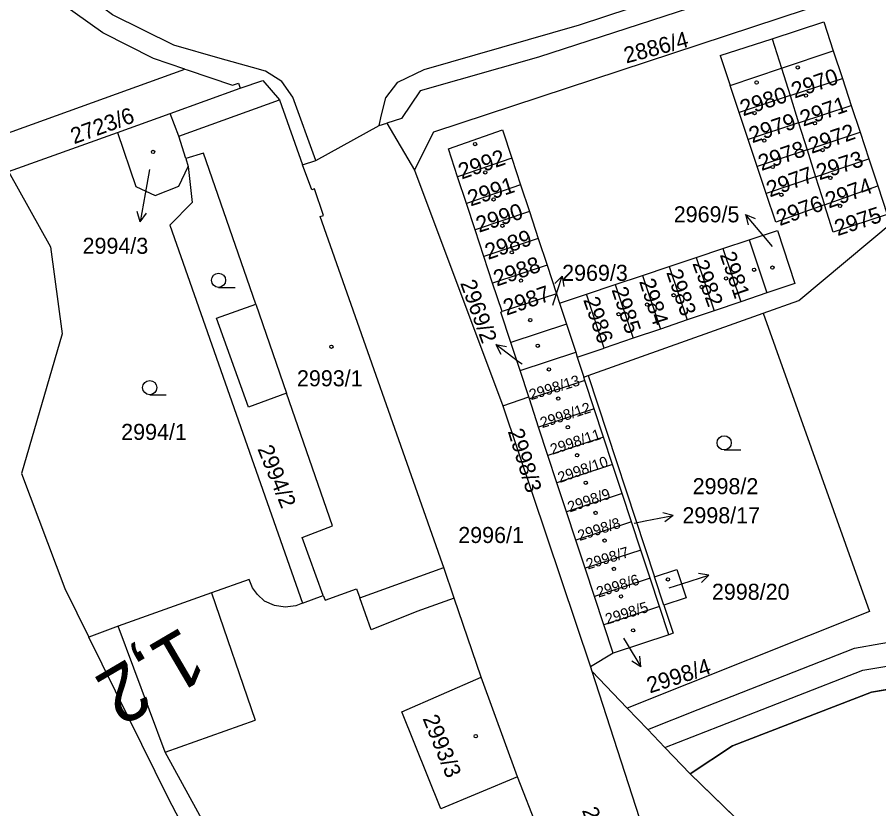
# Model space of a CAD drawing. Extents: x -738085 to -734306, y -1122197 to -1119753.
# Drawn here: x -735225.5 to -735134.3, y -1120249.4 to -1120165.6 of the extents above; entities that cross this region are included whole.
import ezdxf

# ---------------------------------------------------------------- set-up
doc = ezdxf.new("R2010")
doc.units = 0
for name, color, linetype in [('Hranice parcel', 7, 'Continuous'), ('Parcelní čísla', 7, 'Continuous'), ('Pop  PČ popisy', 7, 'Continuous'), ('SŽDC', 7, 'Continuous'), ('Vnitřní kresba', 7, 'Continuous'), ('Vrstva 53', 7, 'Continuous'), ('Vrstva 7', 7, 'Continuous'), ('Značky budov', 7, 'Continuous'), ('Značky kultur', 7, 'Continuous')]:
    doc.layers.add(name, color=color, linetype=linetype)

msp = doc.modelspace()

# ---------------------------------------------------------------- linework, layer by layer
at = {"layer": 'Hranice parcel'}
for p, q in [((-735144.59, -1120170.98), (-735143.67, -1120173.89)), ((-735143.67, -1120173.89), (-735138.14, -1120172.07)), ((-735138.14, -1120172.07), (-735137.2, -1120174.92)), ((-735209.31, -1120175.8), (-735201.89, -1120173.11)), ((-735143.67, -1120173.89), (-735149.07, -1120175.67)), ((-735143.67, -1120173.89), (-735142.77, -1120176.76)), ((-735148.12, -1120178.53), (-735149.07, -1120175.67)), ((-735142.77, -1120176.76), (-735137.2, -1120174.92)), ((-735137.2, -1120174.92), (-735136.26, -1120177.77)), ((-735214.89, -1120177.8), (-735209.31, -1120175.8)), ((-735193.9, -1120180.77), (-735187.2, -1120177.07)), ((-735187.2, -1120177.07), (-735186.39, -1120176.82)), ((-735186.39, -1120176.82), (-735183.44, -1120181.78)), ((-735142.77, -1120176.76), (-735148.12, -1120178.53)), ((-735142.77, -1120176.76), (-735141.86, -1120179.64)), ((-735226.43, -1120181.92), (-735214.89, -1120177.8)), ((-735141.86, -1120179.64), (-735136.26, -1120177.77)), ((-735136.26, -1120177.77), (-735135.33, -1120180.6)), ((-735147.16, -1120181.41), (-735148.12, -1120178.53)), ((-735141.86, -1120179.64), (-735147.16, -1120181.41)), ((-735141.86, -1120179.64), (-735140.97, -1120182.48)), ((-735207.67, -1120180.55), (-735207.41, -1120181.38)), ((-735195.32, -1120181.21), (-735193.9, -1120180.77)), ((-735173.15, -1120180.5), (-735178.88, -1120182.49)), ((-735173.15, -1120180.5), (-735172.22, -1120183.33)), ((-735140.97, -1120182.48), (-735135.33, -1120180.6)), ((-735135.33, -1120180.6), (-735134.39, -1120183.46)), ((-735183.44, -1120181.78), (-735174.09, -1120206.76)), ((-735146.22, -1120184.24), (-735147.16, -1120181.41)), ((-735177.95, -1120185.3), (-735178.88, -1120182.49)), ((-735140.97, -1120182.48), (-735146.22, -1120184.24)), ((-735140.97, -1120182.48), (-735140.03, -1120185.46)), ((-735172.22, -1120183.33), (-735177.95, -1120185.3)), ((-735172.22, -1120183.33), (-735171.28, -1120186.18)), ((-735140.03, -1120185.46), (-735134.39, -1120183.46)), ((-735177.03, -1120188.11), (-735177.95, -1120185.3)), ((-735171.28, -1120186.18), (-735177.03, -1120188.11)), ((-735171.28, -1120186.18), (-735170.35, -1120189.02)), ((-735176.1, -1120190.93), (-735177.03, -1120188.11)), ((-735170.35, -1120189.02), (-735176.1, -1120190.93)), ((-735170.35, -1120189.02), (-735169.41, -1120191.85)), ((-735150.78, -1120190.1), (-735148, -1120189.17)), ((-735148, -1120189.17), (-735146.13, -1120194.79)), ((-735153.61, -1120191.04), (-735150.78, -1120190.1)), ((-735150.78, -1120190.1), (-735148.9, -1120195.73)), ((-735175.17, -1120193.74), (-735176.1, -1120190.93)), ((-735156.46, -1120191.99), (-735153.61, -1120191.04)), ((-735153.61, -1120191.04), (-735151.72, -1120196.68)), ((-735169.41, -1120191.85), (-735175.17, -1120193.74)), ((-735169.41, -1120191.85), (-735168.41, -1120194.89)), ((-735159.3, -1120192.94), (-735156.46, -1120191.99)), ((-735156.46, -1120191.99), (-735154.56, -1120197.65)), ((-735162.18, -1120193.89), (-735159.3, -1120192.94)), ((-735159.3, -1120192.94), (-735157.41, -1120198.61)), ((-735174.17, -1120196.77), (-735175.17, -1120193.74)), ((-735162.18, -1120193.89), (-735160.29, -1120199.59)), ((-735146.13, -1120194.79), (-735148.9, -1120195.73)), ((-735168.41, -1120194.89), (-735174.17, -1120196.77)), ((-735148.9, -1120195.73), (-735151.72, -1120196.68)), ((-735165.05, -1120203.54), (-735146.53, -1120196.94)), ((-735151.72, -1120196.68), (-735154.56, -1120197.65)), ((-735167.36, -1120198.09), (-735173.26, -1120200.03)), ((-735167.36, -1120198.09), (-735166.37, -1120201.08)), ((-735154.56, -1120197.65), (-735157.41, -1120198.61)), ((-735157.41, -1120198.61), (-735160.29, -1120199.59)), ((-735172.27, -1120203.02), (-735173.26, -1120200.03)), ((-735172.27, -1120203.02), (-735166.37, -1120201.08)), ((-735171.35, -1120205.79), (-735172.27, -1120203.02)), ((-735165.52, -1120203.7), (-735165.05, -1120203.54)), ((-735165.39, -1120204.07), (-735165.52, -1120203.7)), ((-735165.05, -1120203.54), (-735158.02, -1120224.86)), ((-735165.39, -1120204.07), (-735171.28, -1120206.01)), ((-735164.41, -1120207.07), (-735165.39, -1120204.07)), ((-735174.09, -1120206.76), (-735171.35, -1120205.79)), ((-735171.28, -1120206.01), (-735171.35, -1120205.79)), ((-735170.3, -1120209), (-735171.28, -1120206.01)), ((-735174.09, -1120206.76), (-735164.81, -1120234.38)), ((-735164.41, -1120207.07), (-735170.3, -1120209)), ((-735163.42, -1120210.06), (-735164.41, -1120207.07)), ((-735169.31, -1120212), (-735170.3, -1120209)), ((-735163.42, -1120210.06), (-735169.31, -1120212)), ((-735162.47, -1120212.95), (-735163.42, -1120210.06)), ((-735168.36, -1120214.89), (-735169.31, -1120212)), ((-735162.47, -1120212.95), (-735168.36, -1120214.89)), ((-735161.46, -1120216.04), (-735162.47, -1120212.95)), ((-735167.34, -1120217.98), (-735168.36, -1120214.89)), ((-735161.46, -1120216.04), (-735167.34, -1120217.98)), ((-735160.47, -1120219.03), (-735161.46, -1120216.04)), ((-735166.36, -1120220.97), (-735167.34, -1120217.98)), ((-735160.47, -1120219.03), (-735166.36, -1120220.97)), ((-735159.48, -1120222.03), (-735160.47, -1120219.03)), ((-735165.37, -1120223.96), (-735166.36, -1120220.97)), ((-735159.48, -1120222.03), (-735165.37, -1120223.96)), ((-735158.49, -1120225.02), (-735159.48, -1120222.03)), ((-735164.38, -1120226.96), (-735165.37, -1120223.96)), ((-735157.04, -1120227.85), (-735158.02, -1120224.86)), ((-735158.49, -1120225.02), (-735164.38, -1120226.96)), ((-735157.51, -1120228.01), (-735158.49, -1120225.02)), ((-735195.3, -1120227.66), (-735196, -1120227.93)), ((-735163.4, -1120229.95), (-735164.38, -1120226.96)), ((-735157.51, -1120228.01), (-735163.4, -1120229.95)), ((-735156.53, -1120231), (-735157.51, -1120228.01)), ((-735214.81, -1120230.09), (-735217.93, -1120231.25)), ((-735162.42, -1120232.94), (-735163.4, -1120229.95)), ((-735156.53, -1120231), (-735162.42, -1120232.94)), ((-735162.42, -1120232.94), (-735164.81, -1120234.38)), ((-735164.81, -1120234.38), (-735164.65, -1120234.85)), ((-735160.91, -1120238.77), (-735164.65, -1120234.85)), ((-735164.65, -1120234.85), (-735158.13, -1120255.05)), ((-735184.78, -1120239.17), (-735176.37, -1120235.48)), ((-735172.55, -1120246.06), (-735176.37, -1120235.48)), ((-735158.75, -1120241.02), (-735160.91, -1120238.77)), ((-735156.93, -1120242.93), (-735158.75, -1120241.02)), ((-735154.27, -1120245.72), (-735156.93, -1120242.93)), ((-735168.74, -1120255.72), (-735172.55, -1120246.06))]:
    msp.add_line(p, q, dxfattribs=at)
for points in [[(-735187.2, -1120177.07), (-735186.92, -1120175.94), (-735186.47, -1120174.12), (-735185.21, -1120172.48), (-735182.42, -1120171.13), (-735165.98, -1120166.38), (-735013.95, -1120116.34), (-735003.48, -1120113.01), (-735000.64, -1120112.19), (-735000, -1120112.13), (-734996.62, -1120111.83), (-734988.63, -1120112.11), (-734951.68, -1120115.51), (-734795.1, -1120131), (-734756.12, -1120134.99), (-734754.2, -1120137.32), (-734753.31, -1120137.78), (-734734.93, -1120139.52), (-734728.17, -1120141.08), (-734724.68, -1120142.84), (-734723.73, -1120143.69)], [(-735193.9, -1120180.77), (-735196.33, -1120174.06), (-735197.48, -1120172.4), (-735199.22, -1120171.31), (-735200.58, -1120170.92), (-735204.03, -1120169.95), (-735208.93, -1120168.56), (-735215.43, -1120165.33), (-735220.17, -1120161.76), (-735223.18, -1120159.07), (-735230.74, -1120150.98), (-735240.02, -1120140.46), (-735244.13, -1120135.8)], [(-735207.77, -1120171.07), (-735211.09, -1120169.95), (-735216.45, -1120167.23), (-735220.95, -1120164.02), (-735226.04, -1120159.26), (-735234.12, -1120150.47), (-735242.12, -1120141.37), (-735242.83, -1120140.56)], [(-735087.85, -1120146.72), (-735088.13, -1120146.35), (-735133.32, -1120161.4), (-735138.8, -1120162.57), (-735140.07, -1120160.51), (-735141.06, -1120160.29), (-735170.32, -1120169.83), (-735182.85, -1120173.37), (-735184.82, -1120176.33), (-735186.39, -1120176.82)], [(-735183.44, -1120181.78), (-735181.38, -1120177.73), (-735088.44, -1120147.09)], [(-735144.59, -1120170.98), (-735139.1, -1120169.14), (-735138.14, -1120172.07)], [(-735228.19, -1120182.96), (-735229.89, -1120179.07), (-735207.77, -1120171.07)], [(-735207.77, -1120171.07), (-735207.53, -1120171.16), (-735202.7, -1120172.79), (-735202.09, -1120172.56), (-735201.89, -1120173.11)], [(-735149.07, -1120175.67), (-735150.03, -1120172.8), (-735144.59, -1120170.98)], [(-735201.89, -1120173.11), (-735199.52, -1120172.3), (-735197.74, -1120174.35), (-735195.32, -1120181.21)], [(-735207.67, -1120180.55), (-735208.4, -1120178.17), (-735209.31, -1120175.8)], [(-735178.88, -1120182.49), (-735179.86, -1120179.52), (-735174.14, -1120177.51), (-735173.15, -1120180.5)], [(-735214.89, -1120177.8), (-735212.94, -1120183.51), (-735210.89, -1120184.46), (-735208.41, -1120183.49), (-735207.41, -1120181.38)], [(-735195.3, -1120227.66), (-735193.1, -1120226.83), (-735195.34, -1120220.68), (-735192.12, -1120219.45), (-735196.99, -1120205.39), (-735201.03, -1120206.88), (-735204.4, -1120197.47), (-735200.25, -1120195.98), (-735205.79, -1120180), (-735207.67, -1120180.55)], [(-735226.43, -1120181.92), (-735221.97, -1120189.91), (-735220.76, -1120199.13), (-735225.06, -1120213.91), (-735220.47, -1120226.11), (-735217.93, -1120231.25)], [(-735207.41, -1120181.38), (-735206.99, -1120185.22), (-735209.34, -1120187.6), (-735195.3, -1120227.66)], [(-735176.37, -1120235.48), (-735179.23, -1120227.13), (-735180.34, -1120223.87), (-735180.47, -1120223.49), (-735193.42, -1120186.69), (-735193.07, -1120186.57), (-735194.04, -1120183.78), (-735194.33, -1120183.88), (-735195.32, -1120181.21)], [(-735134.39, -1120183.46), (-735133.4, -1120186.47), (-735139.12, -1120188.35), (-735140.03, -1120185.46)], [(-735140.03, -1120185.46), (-735145.2, -1120187.29), (-735146.22, -1120184.24)], [(-735146.53, -1120196.94), (-735142.76, -1120195.6), (-735130.27, -1120185.19)], [(-735148, -1120189.17), (-735145.02, -1120188.18), (-735143.17, -1120193.79), (-735146.13, -1120194.79)], [(-735160.29, -1120199.59), (-735163.37, -1120200.63), (-735165.23, -1120194.91), (-735162.18, -1120193.89)], [(-735168.41, -1120194.89), (-735168.09, -1120195.86), (-735167.36, -1120198.09)], [(-735173.26, -1120200.03), (-735174.3, -1120196.83), (-735174.17, -1120196.77)], [(-735146.53, -1120196.94), (-735135.27, -1120228.55), (-735160.91, -1120238.77)], [(-735166.37, -1120201.08), (-735166.21, -1120201.59), (-735165.52, -1120203.7)], [(-735156.93, -1120242.93), (-735151.15, -1120240.68), (-735135.96, -1120234.75), (-735114.78, -1120231.21), (-735102.36, -1120229.14), (-735095.09, -1120227.37), (-735088.56, -1120221.64)], [(-735158.02, -1120224.86), (-735155.65, -1120224.08), (-735154.66, -1120227.07), (-735157.04, -1120227.85)], [(-735154.27, -1120245.72), (-735149.78, -1120242.77), (-735135.06, -1120237.08), (-735101.77, -1120231.55), (-735094.5, -1120229.78), (-735087.7, -1120224.18)], [(-735200.96, -1120225.14), (-735204.93, -1120226.56), (-735214.81, -1120230.09)], [(-735196, -1120227.93), (-735197.14, -1120228.08), (-735198.28, -1120227.9), (-735199.31, -1120227.44), (-735200.08, -1120226.75), (-735200.6, -1120226.01), (-735200.96, -1120225.14)], [(-735157.04, -1120227.85), (-735156.06, -1120230.84), (-735156.53, -1120231)], [(-735158.75, -1120241.02), (-735153.4, -1120238.91), (-735136.86, -1120232.42), (-735134.06, -1120231.94), (-735115.58, -1120228.85)], [(-735197.46, -1120266.06), (-735209.83, -1120243.45), (-735214.81, -1120230.09)], [(-735190.45, -1120282.92), (-735199.82, -1120266.86), (-735209.49, -1120248.33), (-735217.93, -1120231.25)], [(-735172.55, -1120246.06), (-735180.64, -1120249.42), (-735184.78, -1120239.17)], [(-735126.91, -1120271.38), (-735136.63, -1120262.8), (-735138.78, -1120260.72), (-735140.3, -1120259.25), (-735154.27, -1120245.72)]]:
    msp.add_lwpolyline(points, dxfattribs=at)
at = {"layer": 'Pop  PČ popisy'}
for p, q in [((-735211.5, -1120181.72), (-735211.96, -1120184.29)), ((-735211.96, -1120184.29), (-735212.481, -1120187.245)), ((-735212.481, -1120187.245), (-735212.8, -1120186.172)), ((-735212.481, -1120187.245), (-735211.814, -1120186.346)), ((-735146.46, -1120188.77), (-735148.389, -1120186.471)), ((-735148.389, -1120186.471), (-735147.362, -1120186.916)), ((-735148.389, -1120186.471), (-735148.129, -1120187.56)), ((-735145.53, -1120189.88), (-735146.46, -1120188.77)), ((-735168.74, -1120195.85), (-735167.813, -1120192.996)), ((-735167.813, -1120192.996), (-735168.598, -1120193.794)), ((-735167.813, -1120192.996), (-735167.646, -1120194.103)), ((-735168.81, -1120196.07), (-735168.74, -1120195.85)), ((-735172.42, -1120202.07), (-735174.817, -1120200.264)), ((-735174.817, -1120200.264), (-735173.716, -1120200.467)), ((-735174.817, -1120200.264), (-735174.318, -1120201.267)), ((-735172.05, -1120202.35), (-735172.42, -1120202.07)), ((-735159.01, -1120218.94), (-735156.064, -1120218.367)), ((-735156.064, -1120218.367), (-735157.143, -1120218.067)), ((-735156.064, -1120218.367), (-735156.952, -1120219.05)), ((-735160.2, -1120219.18), (-735159.01, -1120218.94)), ((-735155.12, -1120225.6), (-735152.266, -1120224.673)), ((-735152.266, -1120224.673), (-735153.373, -1120224.506)), ((-735152.266, -1120224.673), (-735153.064, -1120225.458)), ((-735156.47, -1120226.04), (-735155.12, -1120225.6)), ((-735161.31, -1120231.35), (-735161.03, -1120231.81)), ((-735161.03, -1120231.81), (-735159.484, -1120234.382)), ((-735159.484, -1120234.382), (-735160.429, -1120233.782)), ((-735159.484, -1120234.382), (-735159.571, -1120233.266))]:
    msp.add_line(p, q, dxfattribs=at)
at = {"layer": 'SŽDC'}
for p, q in [((-735101.77, -1120231.55), (-735135.06, -1120237.08)), ((-735135.06, -1120237.08), (-735149.78, -1120242.77)), ((-735149.78, -1120242.77), (-735154.27, -1120245.72)), ((-735154.27, -1120245.72), (-735140.3, -1120259.25))]:
    msp.add_line(p, q, dxfattribs=at)
at = {"layer": 'Vnitřní kresba'}
for p, q in [((-735145.57, -1120167.86), (-735140.11, -1120166.08)), ((-735140.11, -1120166.08), (-735139.1, -1120169.14)), ((-735151.08, -1120169.65), (-735145.57, -1120167.86)), ((-735145.57, -1120167.86), (-735144.59, -1120170.98)), ((-735151.08, -1120169.65), (-735150.03, -1120172.8)), ((-735208.4, -1120178.17), (-735197.74, -1120174.35)), ((-735168.09, -1120195.86), (-735165.23, -1120194.91)), ((-735200.25, -1120195.98), (-735196.99, -1120205.39)), ((-735166.21, -1120201.59), (-735163.37, -1120200.63)), ((-735189.23, -1120227.08), (-735180.34, -1120223.87)), ((-735204.93, -1120226.56), (-735200.3, -1120240.06)), ((-735192.92, -1120227.35), (-735189.58, -1120226.14)), ((-735189.58, -1120226.14), (-735189.23, -1120227.08)), ((-735193.1, -1120226.83), (-735192.92, -1120227.35)), ((-735188.02, -1120230.49), (-735189.23, -1120227.08)), ((-735179.23, -1120227.13), (-735183.2, -1120228.54)), ((-735183.2, -1120228.54), (-735188.02, -1120230.49)), ((-735209.83, -1120243.45), (-735200.3, -1120240.06))]:
    msp.add_line(p, q, dxfattribs=at)
at = {"layer": 'Vrstva 53'}
for points in [[(-734742.39, -1120198.31), (-734748.46, -1120195.41), (-734799.69, -1120183.7), (-734853.28, -1120170.95), (-734887.03, -1120164.91), (-734913.87, -1120162.91), (-734932.65, -1120163.73), (-734954.75, -1120168.56), (-734977.62, -1120176.17), (-734996.5, -1120184.52), (-735013.84, -1120194.15), (-735022.76, -1120201.89), (-735069.62, -1120231.25), (-735085.17, -1120235.61), (-735095.46, -1120241.5), (-735115.98, -1120262.16), (-735126.91, -1120271.38), (-735136.63, -1120262.8), (-735138.78, -1120260.72), (-735140.3, -1120259.25), (-735154.27, -1120245.72)], [(-735154.27, -1120245.72), (-735149.78, -1120242.77), (-735135.06, -1120237.08), (-735101.77, -1120231.55), (-735094.5, -1120229.78), (-735087.7, -1120224.18), (-735077.88, -1120216.09), (-735062.84, -1120207.4), (-735061.82, -1120206.57), (-735046.74, -1120198.74)]]:
    msp.add_lwpolyline(points, dxfattribs=at)
at = {"layer": 'Značky budov'}
for centre in [(-735142.867, -1120170.909), (-735147.227, -1120172.499), (-735141.997, -1120173.889), (-735147.427, -1120175.739), (-735141.047, -1120176.819), (-735177.027, -1120179.029), (-735146.417, -1120178.649), (-735211.127, -1120179.859), (-735140.237, -1120179.659), (-735175.947, -1120182.019), (-735145.507, -1120181.449), (-735139.397, -1120182.599), (-735175.067, -1120184.879), (-735144.597, -1120184.389), (-735138.377, -1120185.569), (-735174.127, -1120187.679), (-735173.147, -1120190.489), (-735145.537, -1120192.099), (-735147.477, -1120192.329), (-735172.167, -1120193.479), (-735150.447, -1120193.249), (-735153.037, -1120194.159), (-735156.007, -1120195.039), (-735158.817, -1120196.029), (-735171.187, -1120197.669), (-735161.827, -1120197.049), (-735192.247, -1120200.489), (-735170.387, -1120200.389), (-735169.207, -1120202.889), (-735168.227, -1120205.979), (-735167.207, -1120209.009), (-735166.227, -1120211.989), (-735165.307, -1120214.899), (-735164.267, -1120218.089), (-735163.317, -1120221.019), (-735162.327, -1120224.029), (-735156.617, -1120225.129), (-735161.577, -1120226.929), (-735160.297, -1120230.529), (-735207.837, -1120235.039), (-735176.957, -1120241.739)]:
    msp.add_circle(centre, 0.175, dxfattribs=at)
at = {"layer": 'Značky kultur'}
for p, q in [((-735204.193, -1120194.2), (-735202.443, -1120194.2)), ((-735211.483, -1120205.57), (-735209.733, -1120205.57)), ((-735150.653, -1120211.42), (-735148.903, -1120211.42))]:
    msp.add_line(p, q, dxfattribs=at)
for centre in [(-735204.193, -1120193.45), (-735211.483, -1120204.82), (-735150.653, -1120210.67)]:
    msp.add_circle(centre, 0.75, dxfattribs=at)

# ---------------------------------------------------------------- texts
at = {"layer": 'Parcelní čísla'}
for s, height, rotation, p in [('2886/4', 1.7, 15, (-735161.02, -1120170.491)), ('2970', 1.7, 19, (-735143.193, -1120174.213)), ('2980', 1.7, 18, (-735148.647, -1120176.078)), ('2971', 1.7, 19, (-735142.283, -1120177.183)), ('2723/6', 1.7, 20, (-735219.489, -1120179.048)), ('2979', 1.7, 19, (-735147.683, -1120178.943)), ('2972', 1.7, 19, (-735141.403, -1120180.063)), ('2978', 1.7, 19, (-735146.703, -1120181.883)), ('2992', 1.7, 19, (-735178.453, -1120182.783)), ('2973', 1.7, 18, (-735140.577, -1120182.868)), ('2977', 1.7, 20, (-735145.809, -1120184.678)), ('2991', 1.7, 18, (-735177.507, -1120185.638)), ('2974', 1.7, 20, (-735139.569, -1120185.858)), ('2976', 1.7, 20, (-735144.769, -1120187.718)), ('2990', 1.7, 18, (-735176.617, -1120188.418)), ('2975', 1.7, 18, (-735138.647, -1120188.778)), ('2989', 1.7, 19, (-735175.643, -1120191.293)), ('2988', 1.7, 19, (-735174.733, -1120194.123)), ('2981', 1.7, 289, (-735151.133, -1120190.746)), ('2982', 1.7, 290, (-735154.038, -1120191.65)), ('2983', 1.7, 289, (-735156.803, -1120192.606)), ('2969/2', 1.7, 290, (-735178.629, -1120193.737)), ('2984', 1.7, 288, (-735159.678, -1120193.562)), ('2987', 1.7, 19, (-735173.703, -1120197.203)), ('2985', 1.7, 288, (-735162.588, -1120194.442)), ('2986', 1.7, 289, (-735165.593, -1120195.516)), ('2998/13', 1.14, 17, (-735171.103, -1120206.155)), ('2998/12', 1.14, 18, (-735169.923, -1120209.122)), ('2998/3', 1.7, 287, (-735173.582, -1120209.438)), ('2998/11', 1.14, 18, (-735168.853, -1120211.942)), ('2994/2', 1.7, 292, (-735200.098, -1120211.298)), ('2998/10', 1.14, 19, (-735168.044, -1120214.918)), ('2998/9', 1.14, 19, (-735167.004, -1120218.048)), ('2998/8', 1.14, 18, (-735165.953, -1120221.072)), ('2998/7', 1.14, 17, (-735165.083, -1120224.095)), ('2998/6', 1.14, 18, (-735163.963, -1120227.072)), ('2998/5', 1.14, 17, (-735163.043, -1120229.915)), ('2998/4', 1.7, 18, (-735158.524, -1120237.224)), ('2993/3', 1.7, 292, (-735182.608, -1120239.858)), ('2996/2', 1.7, 290, (-735165.729, -1120249.587))]:
    msp.add_text(s, height=height, rotation=rotation, dxfattribs=at).set_placement(p)
for s, p in [('2969/5', (-735155.991, -1120187.31)), ('2994/3', (-735218.591, -1120190.643)), ('2969/3', (-735167.81, -1120193.51)), ('2993/1', (-735195.89, -1120204.68)), ('2994/1', (-735214.5, -1120210.36)), ('2998/2', (-735153.99, -1120216.11)), ('2998/17', (-735155.07, -1120219.19)), ('2996/1', (-735178.81, -1120221.28)), ('2998/20', (-735151.95, -1120227.293))]:
    msp.add_text(s, height=1.7, dxfattribs=at).set_placement(p)
at = {"layer": 'Vrstva 7'}
msp.add_text('1,2', height=6, rotation=210.41497, dxfattribs=at).set_placement((-735207.991, -1120230.047))

doc.saveas('drawing.dxf')
